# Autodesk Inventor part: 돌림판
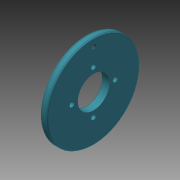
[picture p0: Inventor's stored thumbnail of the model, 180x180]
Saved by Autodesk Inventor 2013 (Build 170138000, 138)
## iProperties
Created: 2019-10
Part Number: 돌림판
Material: 스테인리스강
Document SubType Name: Modeling
Designer: mduedu
Density: 1 g/cm^3
Author: mduedu
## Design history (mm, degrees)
sketch "스케치1" dims "d3" = 30
  geometry: C1 r 32 at (0, 0); C2 r 11 at (0, 0); C3 r 1.7 at (15, 0); C4 r 1.7 at (0, 15); C5 r 1.7 at (-15, 0); C6 r 1.7 at (0, -15); 2 further points
  constraints: 6 centre point, 3 coincident, 2 horizontal alignment, 11 other
  dimensions: "d0" = 64 diameter of C1; "d2" = 3.4 diameter of C3; "d4" = 22 diameter of C2; "d7" = 360 deg dimension on point (0, 0) C3.centre (derived)
extrude "돌출1" new body sketch "스케치1" distance "d9" = 5; taper "d10" = 0 deg
sketch "스케치2" dims "d11" = 54
  geometry: 3 further points
  constraints: 2 vertical alignment, 1 coincident, 2 other
hole "구멍1" sketch "스케치2" at (0, 27) diameter "d13" = 3.242; stored, may be unused: countersink angle "d17" = 90 deg, drill point angle "d19" = 118 deg; dims "d14" = 6, "d15" = 4, "d16" = 2, "d18" = 8
fillet "모깎기1" dims "d20" = 1
node "솔리드1"
